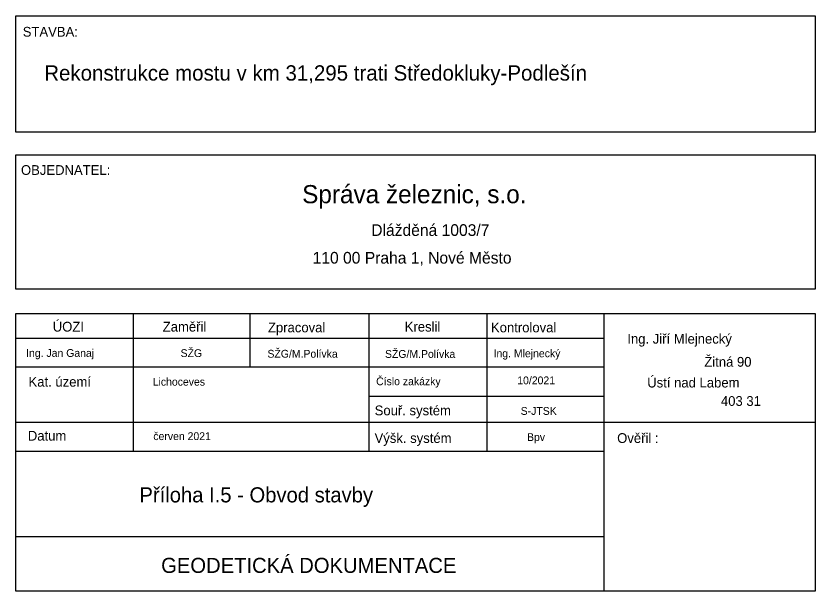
# Model space of a CAD drawing. Extents: x -879530 to -879371, y -1019242 to -1019127.
import ezdxf

# ---------------------------------------------------------------- set-up
doc = ezdxf.new("R2010")
doc.units = 0
doc.layers.add('tabulka', color=7, linetype='Continuous')

msp = doc.modelspace()

# ---------------------------------------------------------------- linework, layer by layer
at = {"layer": 'tabulka'}
for p, q in [((-879530.09, -1019186.45), (-879371.44, -1019186.45)), ((-879506.8, -1019186.45), (-879506.8, -1019213.77)), ((-879483.66, -1019186.45), (-879483.66, -1019197.07)), ((-879460.06, -1019186.45), (-879460.06, -1019213.77)), ((-879436.61, -1019186.45), (-879436.61, -1019213.77)), ((-879413.31, -1019241.58), (-879413.31, -1019186.45)), ((-879530.09, -1019191.36), (-879413.31, -1019191.36)), ((-879530.09, -1019197.07), (-879413.31, -1019197.07)), ((-879460.06, -1019202.88), (-879413.31, -1019202.88)), ((-879530.09, -1019208.07), (-879371.44, -1019208.07)), ((-879530.09, -1019213.77), (-879413.31, -1019213.77)), ((-879530.09, -1019230.76), (-879413.31, -1019230.76))]:
    msp.add_line(p, q, dxfattribs=at)
for points in [[(-879530.09, -1019127.36), (-879371.44, -1019127.36), (-879371.44, -1019150.43), (-879530.09, -1019150.43)], [(-879530.09, -1019154.95), (-879371.44, -1019154.95), (-879371.44, -1019181.64), (-879530.09, -1019181.64)]]:
    msp.add_lwpolyline(points, close=True, dxfattribs=at)
msp.add_lwpolyline([(-879371.44, -1019186.45), (-879371.44, -1019241.58), (-879530.09, -1019241.58), (-879530.09, -1019186.45)], dxfattribs=at)

# ---------------------------------------------------------------- texts
for s, height, p in [('STAVBA:', 1.94, (-879528.75, -1019131.47)), ('Rekonstrukce mostu v km 31,295 trati Středokluky-Podlešín', 3.04, (-879524.48, -1019140.2)), ('OBJEDNATEL:', 1.94, (-879529.1, -1019158.93)), ('Správa železnic, s.o.', 3.61, (-879473.27, -1019164.56)), ('Dlážděná 1003/7', 2.32, (-879459.55, -1019171.05)), ('110 00 Praha 1, Nové Město', 2.32, (-879471.19, -1019176.55)), ('ÚOZI', 1.94, (-879522.79, -1019190.05)), ('Zaměřil', 1.94, (-879500.95, -1019190.05)), ('Zpracoval', 1.94, (-879480.06, -1019190.2)), ('Kreslil', 1.94, (-879452.9, -1019190.05)), ('Kontroloval', 1.94, (-879435.78, -1019190.2)), ('Ing. Jiří Mlejnecký', 1.94, (-879408.71, -1019192.45)), ('Ing. Jan Ganaj', 1.552, (-879528.08, -1019195.08)), ('SŽG', 1.552, (-879497.41, -1019195.11)), ('SŽG/M.Polívka', 1.552, (-879480.16, -1019195.23)), ('SŽG/M.Polívka', 1.552, (-879456.82, -1019195.27)), ('Ing. Mlejnecký', 1.552, (-879435.26, -1019195.15)), ('Žitná 90', 1.94, (-879393.42, -1019197.03)), ('Kat. území', 1.94, (-879527.6, -1019200.99)), ('Lichoceves', 1.552, (-879502.94, -1019200.79)), ('Číslo zakázky', 1.552, (-879458.58, -1019200.7)), ('10/2021', 1.552, (-879430.56, -1019200.52)), ('Ústí nad Labem', 1.94, (-879404.75, -1019201.15)), ('403 31', 1.94, (-879390.12, -1019204.81)), ('Souř. systém', 1.94, (-879458.87, -1019206.68)), ('S-JTSK', 1.552, (-879429.88, -1019206.59)), ('Datum', 1.94, (-879527.74, -1019211.71)), ('červen 2021', 1.552, (-879502.82, -1019211.6)), ('Výšk. systém', 1.94, (-879458.89, -1019212.17)), ('Bpv', 1.552, (-879428.62, -1019211.78)), ('Ověřil :', 1.94, (-879410.72, -1019212.17)), ('Příloha I.5 - Obvod stavby', 3, (-879505.58, -1019223.98)), ('GEODETICKÁ DOKUMENTACE ', 3, (-879501.27, -1019237.99))]:
    msp.add_text(s, height=height, dxfattribs=at).set_placement(p)

doc.saveas('drawing.dxf')
